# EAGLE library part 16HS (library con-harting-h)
CONNECTOR
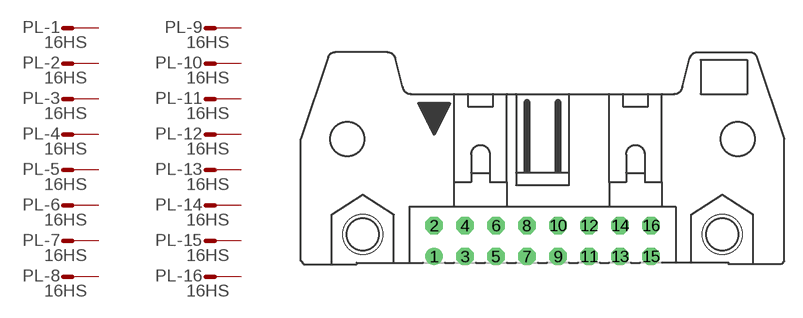
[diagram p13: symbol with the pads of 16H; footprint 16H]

Designator prefix PL; gates -1=M -2=M -3=M -4=M -5=M -6=M -7=M -8=M -9=M -10=M -11=M -12=M -13=M -14=M -15=M -16=M

## 16HS (OC_FARNELL: unknown; OC_NEWARK: unknown)  [16H]
1  -1:S  pas
2  -2:S  pas
3  -3:S  pas
4  -4:S  pas
5  -5:S  pas
6  -6:S  pas
7  -7:S  pas
8  -8:S  pas
9  -9:S  pas
10  -10:S  pas
11  -11:S  pas
12  -12:S  pas
13  -13:S  pas
14  -14:S  pas
15  -15:S  pas
16  -16:S  pas

## Footprint 16H (pad centres in mm)
CONNECTOR
drill 0.914 round: 1 -8.89,-1.27
drill 0.914 octagon: 2 -8.89,1.27; 3 -6.35,-1.27; 4 -6.35,1.27; 5 -3.81,-1.27; 6 -3.81,1.27; 7 -1.27,-1.27; 8 -1.27,1.27; 9 1.27,-1.27; 10 1.27,1.27; 11 3.81,-1.27; 12 3.81,1.27; 13 6.35,-1.27; 14 6.35,1.27; 15 8.89,-1.27; 16 8.89,1.27
hole 3.302 at -14.732,0.533
hole 3.302 at 14.732,0.533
